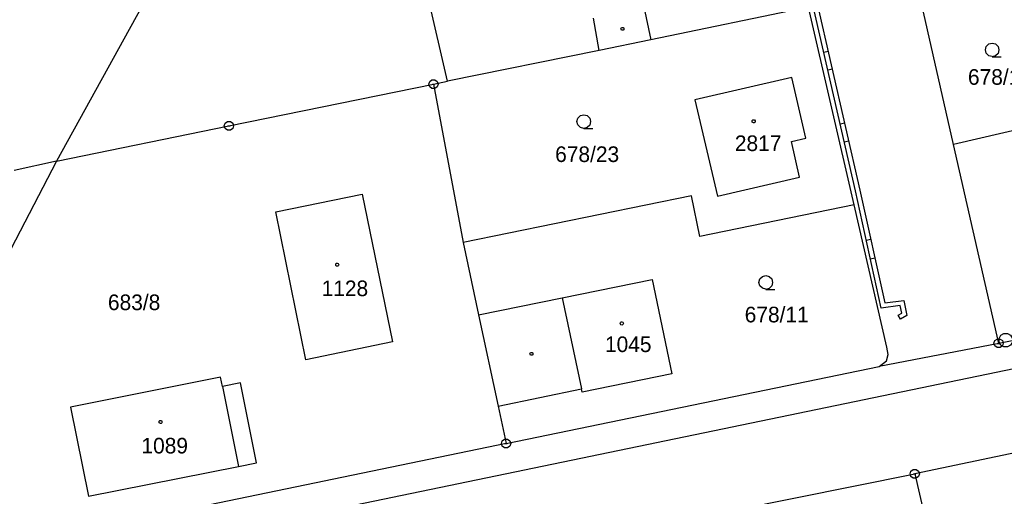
# Model space of a CAD drawing. Extents: x -777309 to -774195, y -1144706 to -1143600.
# Drawn here: x -774633.2 to -774526.2, y -1144641.3 to -1144589.5 of the extents above; entities that cross this region are included whole.
import ezdxf

# ---------------------------------------------------------------- set-up
doc = ezdxf.new("R2010")
doc.units = 0
for name, color, linetype in [('1', 7, 'Continuous'), ('11', 7, 'Continuous'), ('12', 7, 'Continuous'), ('13', 7, 'Continuous'), ('2', 7, 'Continuous'), ('3', 7, 'Continuous'), ('4', 7, 'Continuous'), ('5', 7, 'Continuous'), ('8', 7, 'Continuous')]:
    doc.layers.add(name, color=color, linetype=linetype)

msp = doc.modelspace()

# ---------------------------------------------------------------- linework, layer by layer
at = {"layer": '1'}
for p, q in [((-774586.73, -1144596.18), (-774590.38, -1144580.27)), ((-774618.21, -1144584.94), (-774629.2, -1144604.88)), ((-774531.76, -1144603.07), (-774535.41, -1144586.98)), ((-774547.5, -1144588.12), (-774564.65, -1144591.68)), ((-774542.56, -1144609.62), (-774547.5, -1144588.12)), ((-774570.24, -1144592.83), (-774570.87, -1144589.3)), ((-774564.65, -1144591.68), (-774570.24, -1144592.83)), ((-774570.24, -1144592.83), (-774586.73, -1144596.18)), ((-774549.33, -1144595.78), (-774559.85, -1144598.2)), ((-774547.81, -1144602.38), (-774549.33, -1144595.78)), ((-774610.46, -1144601.04), (-774588.25, -1144596.49)), ((-774588.25, -1144596.49), (-774586.73, -1144596.18)), ((-774588.25, -1144596.49), (-774585.02, -1144613.72)), ((-774559.85, -1144598.2), (-774557.41, -1144608.68)), ((-774519.53, -1144600.21), (-774531.76, -1144603.07)), ((-774629.2, -1144604.88), (-774610.46, -1144601.04)), ((-774549.37, -1144602.74), (-774547.81, -1144602.38)), ((-774548.48, -1144606.61), (-774549.37, -1144602.74)), ((-774526.85, -1144624.69), (-774531.76, -1144603.07)), ((-774629.2, -1144604.88), (-774638.93, -1144623.56)), ((-774629.2, -1144604.88), (-774633.79, -1144605.87)), ((-774557.41, -1144608.68), (-774548.48, -1144606.61)), ((-774605.38, -1144610.38), (-774595.98, -1144608.46)), ((-774595.98, -1144608.46), (-774592.7, -1144624.53)), ((-774560.22, -1144608.64), (-774585.02, -1144613.72)), ((-774559.32, -1144613.05), (-774560.22, -1144608.64)), ((-774542.56, -1144609.62), (-774559.32, -1144613.05)), ((-774539.01, -1144625.09), (-774542.56, -1144609.62)), ((-774602.1, -1144626.46), (-774605.38, -1144610.38)), ((-774585.02, -1144613.72), (-774583.35, -1144621.57)), ((-774574.25, -1144619.72), (-774564.48, -1144617.74)), ((-774564.48, -1144617.74), (-774562.34, -1144627.98)), ((-774583.35, -1144621.57), (-774574.25, -1144619.72)), ((-774583.35, -1144621.57), (-774581.23, -1144631.51)), ((-774514.84, -1144622.23), (-774526.85, -1144624.69)), ((-774592.7, -1144624.53), (-774602.1, -1144626.46)), ((-774526.85, -1144624.69), (-774539.82, -1144627.2)), ((-774539.04, -1144626.59), (-774538.86, -1144625.9)), ((-774538.86, -1144625.9), (-774539.01, -1144625.09)), ((-774539.82, -1144627.2), (-774539.04, -1144626.59)), ((-774580.36, -1144635.59), (-774539.82, -1144627.2)), ((-774562.34, -1144627.98), (-774572.11, -1144630)), ((-774611.38, -1144628.35), (-774627.68, -1144631.62)), ((-774611.17, -1144629.37), (-774611.38, -1144628.35)), ((-774609.21, -1144628.98), (-774611.17, -1144629.37)), ((-774607.46, -1144637.67), (-774609.21, -1144628.98)), ((-774581.23, -1144631.51), (-774572.18, -1144629.64)), ((-774572.11, -1144630), (-774572.18, -1144629.64)), ((-774627.68, -1144631.62), (-774625.71, -1144641.31)), ((-774581.23, -1144631.51), (-774580.36, -1144635.59)), ((-774580.36, -1144635.59), (-774643.21, -1144648.56)), ((-774524.21, -1144636.39), (-774535.97, -1144638.87)), ((-774609.43, -1144638.06), (-774607.46, -1144637.67)), ((-774625.71, -1144641.31), (-774609.43, -1144638.06)), ((-774555.59, -1144642.81), (-774535.97, -1144638.87)), ((-774535.97, -1144638.87), (-774531.47, -1144658.33))]:
    msp.add_line(p, q, dxfattribs=at)
at = {"layer": '11'}
msp.add_lwpolyline([(-774846.81, -1144686.15), (-774837, -1144688.5), (-774835.67, -1144688.28), (-774747.5, -1144673.5), (-774460.5, -1144614), (-774409.76, -1144605.57)], dxfattribs=at)
at = {"layer": '12'}
for p, q in [((-774549.33, -1144595.78), (-774559.85, -1144598.2)), ((-774547.81, -1144602.38), (-774549.33, -1144595.78)), ((-774559.85, -1144598.2), (-774557.41, -1144608.68)), ((-774549.37, -1144602.74), (-774547.81, -1144602.38)), ((-774548.48, -1144606.61), (-774549.37, -1144602.74)), ((-774557.41, -1144608.68), (-774548.48, -1144606.61)), ((-774605.38, -1144610.38), (-774595.98, -1144608.46)), ((-774595.98, -1144608.46), (-774592.7, -1144624.53)), ((-774602.1, -1144626.46), (-774605.38, -1144610.38)), ((-774574.25, -1144619.72), (-774564.48, -1144617.74)), ((-774564.48, -1144617.74), (-774562.34, -1144627.98)), ((-774574.25, -1144619.72), (-774572.18, -1144629.64)), ((-774592.7, -1144624.53), (-774602.1, -1144626.46)), ((-774562.34, -1144627.98), (-774572.11, -1144630)), ((-774611.38, -1144628.35), (-774627.68, -1144631.62)), ((-774611.17, -1144629.37), (-774611.38, -1144628.35)), ((-774611.17, -1144629.37), (-774609.43, -1144638.06)), ((-774572.11, -1144630), (-774572.18, -1144629.64)), ((-774627.68, -1144631.62), (-774625.71, -1144641.31)), ((-774625.71, -1144641.31), (-774609.43, -1144638.06))]:
    msp.add_line(p, q, dxfattribs=at)
at = {"layer": '13'}
for p, q in [((-774542.4, -1144608.11), (-774547.07, -1144587.7)), ((-774546.59, -1144587.58), (-774541.92, -1144608.01)), ((-774545.36, -1144592.94), (-774545.85, -1144593.05)), ((-774545.41, -1144594.95), (-774544.92, -1144594.84)), ((-774543.58, -1144600.74), (-774544.07, -1144600.85)), ((-774543.63, -1144602.75), (-774543.14, -1144602.64)), ((-774539.62, -1144620.85), (-774542.4, -1144608.11)), ((-774541.92, -1144608.01), (-774539.22, -1144620.29)), ((-774540.74, -1144613.38), (-774541.23, -1144613.49)), ((-774540.79, -1144615.48), (-774540.3, -1144615.37))]:
    msp.add_line(p, q, dxfattribs=at)
msp.add_lwpolyline([(-774539.22, -1144620.29), (-774537.16, -1144620.02), (-774536.82, -1144621.65), (-774537.53, -1144622.04), (-774537.77, -1144621.6), (-774537.38, -1144621.39), (-774537.56, -1144620.58), (-774539.62, -1144620.85)], dxfattribs=at)
at = {"layer": '3'}
for points in [[(-774527.55, -1144593.5), (-774527.93, -1144593.4), (-774528.2, -1144593.13), (-774528.3, -1144592.76), (-774528.2, -1144592.39), (-774527.93, -1144592.12), (-774527.56, -1144592.02), (-774527.19, -1144592.12), (-774526.92, -1144592.39), (-774526.82, -1144592.77), (-774526.92, -1144593.15), (-774527.19, -1144593.42), (-774527.57, -1144593.52), (-774526.57, -1144593.52)], [(-774571.91, -1144601.3), (-774572.29, -1144601.2), (-774572.56, -1144600.93), (-774572.66, -1144600.56), (-774572.56, -1144600.19), (-774572.29, -1144599.92), (-774571.92, -1144599.82), (-774571.55, -1144599.92), (-774571.28, -1144600.19), (-774571.18, -1144600.57), (-774571.28, -1144600.95), (-774571.55, -1144601.22), (-774571.93, -1144601.32), (-774570.93, -1144601.32)], [(-774552.14, -1144618.79), (-774552.52, -1144618.69), (-774552.79, -1144618.42), (-774552.89, -1144618.05), (-774552.79, -1144617.68), (-774552.52, -1144617.41), (-774552.15, -1144617.31), (-774551.78, -1144617.41), (-774551.51, -1144617.68), (-774551.41, -1144618.06), (-774551.51, -1144618.44), (-774551.78, -1144618.71), (-774552.16, -1144618.81), (-774551.16, -1144618.81)]]:
    msp.add_lwpolyline(points, dxfattribs=at)
at = {"layer": '4'}
for p, q in [((-774565.39, -1144588.08), (-774564.65, -1144591.68)), ((-774574.25, -1144619.72), (-774572.18, -1144629.64)), ((-774611.17, -1144629.37), (-774609.43, -1144638.06))]:
    msp.add_line(p, q, dxfattribs=at)
at = {"layer": '5'}
for points in [[(-774567.63, -1144590.32), (-774567.54, -1144590.47), (-774567.63, -1144590.62), (-774567.81, -1144590.62), (-774567.9, -1144590.47), (-774567.81, -1144590.32)], [(-774553.47, -1144600.37), (-774553.37, -1144600.39), (-774553.32, -1144600.48), (-774553.3, -1144600.54), (-774553.32, -1144600.63), (-774553.4, -1144600.7), (-774553.47, -1144600.71), (-774553.56, -1144600.68), (-774553.62, -1144600.62), (-774553.64, -1144600.54), (-774553.62, -1144600.45), (-774553.54, -1144600.38)], [(-774598.7, -1144615.96), (-774598.6, -1144615.98), (-774598.55, -1144616.07), (-774598.53, -1144616.13), (-774598.55, -1144616.22), (-774598.63, -1144616.29), (-774598.7, -1144616.3), (-774598.79, -1144616.27), (-774598.85, -1144616.21), (-774598.87, -1144616.13), (-774598.85, -1144616.04), (-774598.77, -1144615.97)], [(-774567.79, -1144622.35), (-774567.69, -1144622.37), (-774567.64, -1144622.46), (-774567.62, -1144622.52), (-774567.64, -1144622.61), (-774567.72, -1144622.68), (-774567.79, -1144622.69), (-774567.88, -1144622.66), (-774567.94, -1144622.6), (-774567.96, -1144622.52), (-774567.94, -1144622.43), (-774567.86, -1144622.36)], [(-774577.52, -1144625.67), (-774577.43, -1144625.82), (-774577.52, -1144625.97), (-774577.7, -1144625.97), (-774577.79, -1144625.82), (-774577.7, -1144625.67)], [(-774617.89, -1144633.07), (-774617.79, -1144633.09), (-774617.74, -1144633.18), (-774617.72, -1144633.24), (-774617.74, -1144633.33), (-774617.82, -1144633.4), (-774617.89, -1144633.41), (-774617.98, -1144633.38), (-774618.04, -1144633.32), (-774618.06, -1144633.24), (-774618.04, -1144633.15), (-774617.96, -1144633.08)]]:
    msp.add_lwpolyline(points, close=True, dxfattribs=at)
at = {"layer": '8'}
for p, q in [((-774588.37, -1144596.49), (-774588.13, -1144596.49)), ((-774610.58, -1144601.04), (-774610.34, -1144601.04)), ((-774526.97, -1144624.69), (-774526.73, -1144624.69)), ((-774580.48, -1144635.59), (-774580.24, -1144635.59)), ((-774536.09, -1144638.87), (-774535.85, -1144638.87))]:
    msp.add_line(p, q, dxfattribs=at)
for points in [[(-774588.1, -1144596.01), (-774587.85, -1144596.19), (-774587.75, -1144596.48), (-774587.85, -1144596.77), (-774588.1, -1144596.95), (-774588.41, -1144596.95), (-774588.66, -1144596.77), (-774588.76, -1144596.48), (-774588.66, -1144596.19), (-774588.41, -1144596.01)], [(-774610.31, -1144600.56), (-774610.06, -1144600.74), (-774609.96, -1144601.03), (-774610.06, -1144601.32), (-774610.31, -1144601.5), (-774610.62, -1144601.5), (-774610.87, -1144601.32), (-774610.97, -1144601.03), (-774610.87, -1144600.74), (-774610.62, -1144600.56)], [(-774525.89, -1144623.62), (-774525.55, -1144623.81), (-774525.36, -1144624.15), (-774525.36, -1144624.54), (-774525.55, -1144624.88), (-774525.89, -1144625.07), (-774526.28, -1144625.07), (-774526.62, -1144624.88), (-774526.81, -1144624.54), (-774526.81, -1144624.15), (-774526.62, -1144623.81), (-774526.28, -1144623.62)], [(-774526.7, -1144624.21), (-774526.45, -1144624.39), (-774526.35, -1144624.68), (-774526.45, -1144624.97), (-774526.7, -1144625.15), (-774527.01, -1144625.15), (-774527.26, -1144624.97), (-774527.36, -1144624.68), (-774527.26, -1144624.39), (-774527.01, -1144624.21)], [(-774580.21, -1144635.11), (-774579.96, -1144635.29), (-774579.86, -1144635.58), (-774579.96, -1144635.87), (-774580.21, -1144636.05), (-774580.52, -1144636.05), (-774580.77, -1144635.87), (-774580.87, -1144635.58), (-774580.77, -1144635.29), (-774580.52, -1144635.11)], [(-774535.82, -1144638.39), (-774535.57, -1144638.57), (-774535.47, -1144638.86), (-774535.57, -1144639.15), (-774535.82, -1144639.33), (-774536.13, -1144639.33), (-774536.38, -1144639.15), (-774536.48, -1144638.86), (-774536.38, -1144638.57), (-774536.13, -1144638.39)]]:
    msp.add_lwpolyline(points, close=True, dxfattribs=at)

# ---------------------------------------------------------------- texts
at = {"layer": '2'}
for s, p in [('678/10', (-774530.19, -1144596.56)), ('2817', (-774555.51, -1144603.77)), ('678/23', (-774575.03, -1144604.96)), ('1128', (-774600.4, -1144619.55)), ('683/8', (-774623.61, -1144621.07)), ('678/11', (-774554.44, -1144622.4)), ('1045', (-774569.62, -1144625.63)), ('1089', (-774619.97, -1144636.66))]:
    msp.add_text(s, height=1.7, dxfattribs=at).set_placement(p)

doc.saveas('drawing.dxf')
